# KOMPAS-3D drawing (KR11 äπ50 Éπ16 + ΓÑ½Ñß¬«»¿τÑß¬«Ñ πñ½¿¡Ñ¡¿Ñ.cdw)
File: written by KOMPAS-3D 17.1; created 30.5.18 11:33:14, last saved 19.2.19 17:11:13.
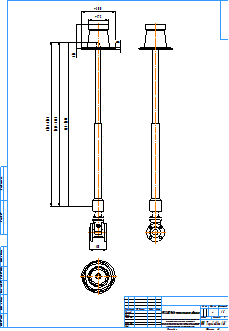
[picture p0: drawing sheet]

Sheet 1: A2, portrait

Title block, sheet 1: name: KR11 Ду50 Ру16 + телескопическое удлинение; sheets: 1; sheet format: A2; stored path: C:\Users\kka\KOMPAS_Work\!Trash\ГРАНАР KR Задвижки с приводами и удлинениями\С удлинениями\KR11 Ду50 Ру16 + телескопическое удлинение.cdw

Views: Вид 1, Проекционный вид 3
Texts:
  kka
  adl
  Рама для чертежей
  Лит-Масса-Масштаб
  Материал-Предприятие
  Масштаб
  Изм.
  Лист
  № докум.
  Подп.
  Дата
  Лит.
  Разраб.
  Пров.
  Т.контр.
  Листов
  Внимание! Данный продукт является объектом авторского права ООО «Торговый Дом АДЛ».
  Запрещается изменение, копирование, распространение
  (в том числе путем копирования на другие сайты и ресурсы в Интернете)
  или любое иное использование информации и объектов без предварительного
  согласия правообладателя (ООО «Торговый Дом АДЛ»).
  Н.контр.
  Утв.
  ООО "Торговый дом АДЛ"
  Изменение
  Номер документа
  Подпись
  Обозначение документа
  Наименование изделия
  Масса изделия по ГОСТ 2.109-73
  Порядковый номер листа
  Общее количество листов в документе
  Характер работы, выполненной лицом, подписавшим документ
  Наименование или индекс предприятия, выпускающего документ
  Инв. № подл.
  Подп. и дата
  Взам. инв. №
  Инв. № дубл.
  Инвентарный номер подлинника по ГОСТ 2.501-68
  Подпись принявшего подлинник в отдел технической документации
  Инвентарный номер подлинника, взамен которого выпущен данный подлинник
  Инвентарный номер дубликата по ГОСТ 2.502-68
  Подпись принявшего дубликат в отдел технической документации
  Справ. №
  Перв. примен.
  Обозначение документа, взамен или на основании которого выпущен данный документ
  Обозначение документа, в котором впервые записан данный документ
  Подпись лица, копировавшего чертеж
  Обозначение формата листа
  !Рама для чертежа
Dimensions and other numbers on the sheet: 846-; 1465; 1547-2865; 2160-3160; 300; 18; 210; 175; 150; 1:5; 1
